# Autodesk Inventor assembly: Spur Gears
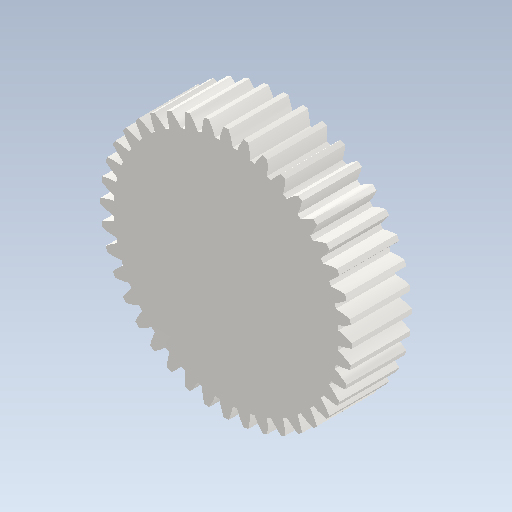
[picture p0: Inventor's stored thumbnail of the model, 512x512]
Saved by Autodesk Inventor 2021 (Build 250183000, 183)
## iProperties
ClientObjectVersion: 1
Created: 2021-07
Part Number: Spur Gears
Document SubType Name: Assembly
Designer: CHIRAG
Categories: <?xml version="1.0" encoding="UTF-16"?> <MemberInstance><Categories><FamilyTemplate/><ParamToTemplateMap><ParamToTemplate><ParamToTemplate CategoryParameter="//
Author: CHIRAG
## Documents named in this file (2)
- C:\Users\CHIRAG\Documents\Assembly2\Assembly2\trail.2\Design Accelerator\Spur Gears6.iam
- C:\Users\CHIRAG\Documents\Assembly2\Assembly2\trail.2\Design Accelerator\Spur Gear23.ipt
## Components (1 placed, 1 different names)
1. Spur Gear2:1
